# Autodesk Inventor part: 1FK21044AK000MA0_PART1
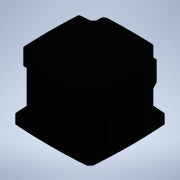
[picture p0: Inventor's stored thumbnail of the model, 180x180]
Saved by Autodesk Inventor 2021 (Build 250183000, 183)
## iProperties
Created: 2025-04
Part Number: 1FK21044AK000MA0_PART1
Material: Generic
Catalog Web Link: www.3dfindit.com
Description: -Servo synchronous motor
Document SubType Name: Modeling
Designer: psAdmin
Mass: 314.393 g
Surface Area: 353.669 cm^2
Volume: 314.393 cm^3
Density: 1 g/cm^3
Appearance: PSOLRGB-176-176-176
Category: PARTsolutions
Title: 1FK21044AK000MA0_PART1
Author: Cadenas PARTsolutions
Comments: Servo synchronous motor
Sending System: PARTsolutions
Preprocessor: ST-DEVELOPER v19.3
PSOL_IDENT_0: {$CADENAS_DATA/23d-libs/siemens_ag/_cat_/87/f4/1fk21044ak000ma0.prj},213 {VTYP=3D},{NB=1FK21044AK000
PSOL_IDENT_1: MA0_PART1},{LINA=1FK21044AK000MA0_PART1},{NN=1FK21044AK000MA0_PART1},{NOPRJ=TRUE},{DATE=19.08.2025 1
PSOL_IDENT_2: 4:00:48},{GEOMDATE=30.07.2025 02:00:50},{VERSION=},{LINEID=10},{WBVAR=},{WBNUMERIC=}  {NB=1FK21044AK
PSOL_IDENT_3: 000MA0_PART1},{LINA=1FK21044AK000MA0_PART1},{KT=DUMMY},{PREVIEW=../../../_pool_/cb/72/p_d211_xx_0043
PSOL_IDENT_4: 4j.png},{DESCSHORT=SIMOTICS S-1FK2 HD, SINAMICS S210 3AC 400V-480V, 0.95 Nm, 6000 rpm},{DESCLONG=SIM
PSOL_IDENT_5: OTICS S-1FK2 HD servo motor M0=1.27 Nm; PN = 0.6 kW at nN=6000 rpm (380-480 V); PN = 0.4 kW at nN=30
PSOL_IDENT_6: 00 rpm (200-240 V); degree of protection IP64; cylindrical shaft D19x40mm; absolute encoder 22-bit +
PSOL_IDENT_7: 12-bit multiturn (encoder AM22DQC); with OCC interface; plug size M17, rotatable; SIMOTICS S-1FK2 s
PSOL_IDENT_8: ervomotorfor a wide range of uses in industrial environments. SIMOTICS S‑1FK2 servomotors are compac
PSOL_IDENT_9: t synchronous motors with a high dynamic performance that set themselves apart as a result of their
PSOL_IDENT_10: high power density, degree of protection and overload capability. The motors are available in two va
PSOL_IDENT_11: riants: as High Dynamic variant (highest dynamic performance as a result of the low intrinsic moment
PSOL_IDENT_12: of inertia for applications demanding a high dynamic performance with low moved masses) - and as Co
PSOL_IDENT_13: mpact variant (precise and stable closed-loop control for medium up to large moved masses as a resul
PSOL_IDENT_14: t of a medium intrinsic moment of inertia). SIMOTICSS‑1FK2 servomotors fully exploit their strengths
PSOL_IDENT_15: in a system with the SINAMICSS210 frequency converter and simple connection using the one cable con
PSOL_IDENT_16: nection (OCC). Advantages include the short control and positioning times, fast and precise correcti
PSOL_IDENT_17: on of disturbing quantities as well as stable control with a high dynamic performance. The servo mot
PSOL_IDENT_18: ors can be configured to address a wide range of requirements. For example with and without holding
PSOL_IDENT_19: brake, IP64 or IP65 degree of protection, singleturn or multiturn absolute encoders - to name just a
PSOL_IDENT_20: few. Further, the servomotors are available in different shaft heights extending from 20 to 100. A
PSOL_IDENT_21: shaft sealing ring is available to achieve an IP65 degree of protection and for subsequent mounting
PSOL_IDENT_22: at the motor or as spare part. SIMOTICS - the optimum motor for each and every motion control applic
PSOL_IDENT_23: ation.},{INTNO=195125056312},{SUPPLIERALTNO=1FK2104-4AK00-0MA0},{MANUID=1FK21044AK000MA0},{MANUNAME=
PSOL_IDENT_24: Siemens},{MANUTYPEDESC=Synchronous motor 1FK2-HD 1,27 Nm},{AAU732=SIMOTICS},{AAO057=S-1FK2},{AAU734=
PSOL_IDENT_25: SIMOTICS S-1FK2 HD servo motor M0=1.27 Nm; PN = 0.6 kW at nN=6000 rpm (380-480 V); PN = 0.4 kW at nN=
PSOL_IDENT_26: 3000 rpm (200-240 V); degree of protection IP64; cylindrical shaft D19x40mm; absolute encoder 22-bit
PSOL_IDENT_27: + 12-bit multiturn (encoder AM22DQC); with OCC interface; plug size M17, rotatable;},{AAW338=Synchr
PSOL_IDENT_28: onous motor 1FK2-HD 1,27 Nm},{AAO742=SIMOTICS},{AAO663=4042948690994},{NOCUPEROU=1},{PRICEQUANTITY=1
PSOL_IDENT_29: },{QUANTITYMIN=1},{QUANTITYINT=1},{CTN=85015100},{COO=DE},{AAO676=1FK2104-4AK00-0MA0},{AAO677=Siemen
PSOL_IDENT_30: s AG},{ORDERUNIT=C62},{CONTENTUNIT=C62}
NB: 1FK21044AK000MA0_PART1
NT: Servo synchronous motor
NBSYN: $MANUID._PART1
LINA: 1FK21044AK000MA0_PART1
CATALOG: SIEMENS
PREVIEW: ../../../_pool_/cb/72/p_d211_xx_00434j.png
DESCSHORT: SIMOTICS S-1FK2 HD, SINAMICS S210 3AC 400V-480V, 0.95 Nm, 6000 rpm
DESCLONG: SIMOTICS S-1FK2 HD servo motor M0=1.27 Nm; PN = 0.6 kW at nN=6000 rpm (380-480 V); PN = 0.4 kW at nN=3000 rpm (200-240 V); degree of protection IP64; cylindrica
INTNO: 195125056312
SUPPLIERALTNO: 1FK2104-4AK00-0MA0
MANUID: 1FK21044AK000MA0
MANUNAME: Siemens
MANUTYPEDESC: Synchronous motor 1FK2-HD 1,27 Nm
AAU732: SIMOTICS
AAO057: S-1FK2
AAU734: SIMOTICS S-1FK2 HD servo motor M0=1.27 Nm; PN = 0.6 kW at nN=6000 rpm (380-480 V); PN = 0.4 kW at nN=3000 rpm (200-240 V); degree of protection IP64; cylindrica
AAW338: Synchronous motor 1FK2-HD 1,27 Nm
AAO742: SIMOTICS
AAO663: 4042948690994.0
NOCUPEROU: 1
PRICEQUANTITY: 1
QUANTITYMIN: 1
QUANTITYINT: 1
CTN: 85015100
COO: DE
ARTICLENO: 1FK21044AK000MA0_PART1
BOMINFO: 1FK21044AK000MA0_PART1
CREATOR: CADENAS GmbH
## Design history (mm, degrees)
feature "2025_04_17_15_37_40_0431"
node "ECLASS_CAX_IMPORTER_001_CP_0_XY"
node "ECLASS_CAX_IMPORTER_001_CP_0_YZ"
node "ECLASS_CAX_IMPORTER_001_CP_0_ZX"
node "ECLASS_CAX_IMPORTER_001_CP_0_X"
node "ECLASS_CAX_IMPORTER_001_CP_0_Y"
node "ECLASS_CAX_IMPORTER_001_CP_0_Z"
node "ECLASS_CAX_IMPORTER_001_CP_0_Center"
node "ECLASS_CAX_IMPORTER_001_CP_1_XY"
node "ECLASS_CAX_IMPORTER_001_CP_1_YZ"
node "ECLASS_CAX_IMPORTER_001_CP_1_ZX"
node "ECLASS_CAX_IMPORTER_001_CP_1_X"
node "ECLASS_CAX_IMPORTER_001_CP_1_Y"
node "ECLASS_CAX_IMPORTER_001_CP_1_Z"
node "ECLASS_CAX_IMPORTER_001_CP_1_Center"
body "Solid1"
